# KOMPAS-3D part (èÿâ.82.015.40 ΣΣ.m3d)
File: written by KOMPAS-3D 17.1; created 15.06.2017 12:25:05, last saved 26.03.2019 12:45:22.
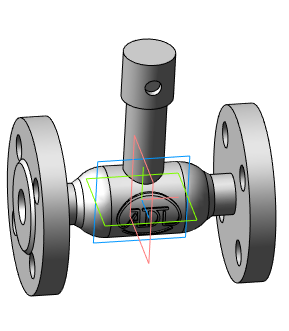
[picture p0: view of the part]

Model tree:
1. Операция без истории:2  (labels: Сталь 20  ГОСТ 1050-88)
